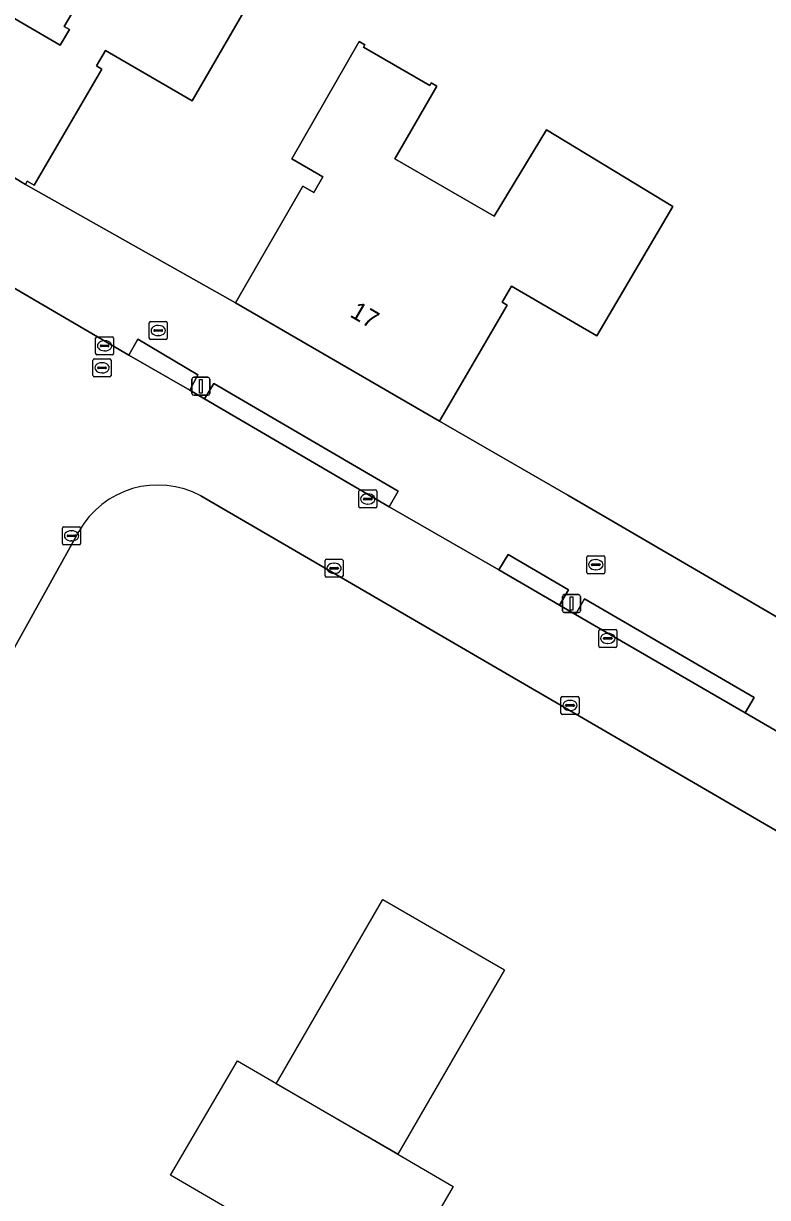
# Model space of a CAD drawing. Extents: x 156502 to 159075, y 384229 to 386100.
# Drawn here: x 157195.8 to 157237.2, y 385818.9 to 385884.2 of the extents above; entities that cross this region are included whole.
import ezdxf

# ---------------------------------------------------------------- set-up
doc = ezdxf.new("R2010")
doc.units = 0
for name, color, linetype in [('IMGEO_Brandkraan', 7, 'Continuous'), ('IMGEO_Erf', 7, 'Continuous'), ('IMGEO_Grasland_overig', 7, 'Continuous'), ('IMGEO_Groenvoorziening', 7, 'Continuous'), ('IMGEO_Haag', 7, 'Continuous'), ('IMGEO_Hek', 7, 'Continuous'), ('IMGEO_Kolk', 7, 'Continuous'), ('IMGEO_Lichtmast', 7, 'Continuous'), ('IMGEO_Pand', 7, 'Continuous'), ('IMGEO_Pand_nummerreeks', 7, 'Continuous'), ('IMGEO_Pand_vergunning_verleend', 7, 'Continuous'), ('IMGEO_Rijbaan_lokaal_open', 7, 'Continuous'), ('IMGEO_Rioolput', 7, 'Continuous'), ('IMGEO_Voetpad_open', 7, 'Continuous')]:
    doc.layers.add(name, color=color, linetype=linetype)

msp = doc.modelspace()

# ---------------------------------------------------------------- linework, layer by layer
at = {"layer": 'IMGEO_Brandkraan'}
for p, q in [((157227.135, 385853.685), (157227.135, 385854.537)), ((157227.21, 385854.611), (157228.062, 385854.611)), ((157227.623, 385854.391), (157227.648, 385854.391)), ((157228.136, 385854.537), (157228.136, 385853.685)), ((157227.394, 385854.105), (157227.394, 385854.117)), ((157227.832, 385854.068), (157227.434, 385854.068)), ((157227.437, 385854.154), (157227.835, 385854.154)), ((157227.646, 385853.831), (157227.621, 385853.831)), ((157227.878, 385854.117), (157227.878, 385854.105)), ((157228.062, 385853.611), (157227.21, 385853.611))]:
    msp.add_line(p, q, dxfattribs=at)
for points in [[(157227.135, 385853.685), (157227.135, 385854.537)], [(157227.21, 385854.611), (157228.062, 385854.611)], [(157228.136, 385854.537), (157228.136, 385853.685)], [(157228.062, 385853.611), (157227.21, 385853.611)]]:
    msp.add_lwpolyline(points, dxfattribs=at)
for centre, radius, start, end in [((157227.212, 385854.535), 0.0765, 91.55205, 178.44795), ((157227.212, 385854.535), 0.0765, 91.55205, 178.44795), ((157228.06, 385854.535), 0.0765, 1.55205, 88.44795), ((157228.06, 385854.535), 0.0765, 1.55205, 88.44795), ((157227.212, 385853.687), 0.0765, 181.55205, 268.44795), ((157227.212, 385853.687), 0.0765, 181.55205, 268.44795), ((157227.434, 385854.114), 0.0403, 85.87752, 175.75265), ((157227.431, 385854.104), 0.0366, 178.93798, 274.71019), ((157227.835, 385854.111), 0.043, 264.86636, 352.45326), ((157227.839, 385854.116), 0.0386, 1.73085, 96.63898), ((157228.06, 385853.687), 0.0765, 271.55205, 358.44795), ((157228.06, 385853.687), 0.0765, 271.55205, 358.44795)]:
    msp.add_arc(centre, radius, start, end, dxfattribs=at)
for centre, major_axis, ratio, start_param, end_param in [((157227.622, 385854.111), (-0.387, 0.002), 0.722429, 4.712389, 7.853982), ((157227.647, 385854.111), (-0.39, 0.002), 0.717154, 1.570796, 4.712389)]:
    msp.add_ellipse(centre, major_axis=major_axis, ratio=ratio, start_param=start_param, end_param=end_param, dxfattribs=at)
at = {"layer": 'IMGEO_Erf'}
for points in [[(157188.853, 385888.249), (157197.887, 385882.973), (157198.399, 385883.845), (157198.106, 385884.017), (157202.417, 385891.356)], [(157209.465, 385887.215), (157205.225, 385879.893), (157200.407, 385882.684), (157199.904, 385881.82), (157200.198, 385881.649), (157196.439, 385875.192), (157196.06, 385875.413), (157195.952, 385875.233), (157207.627, 385868.664), (157211.365, 385875.15), (157211.978, 385874.797), (157212.478, 385875.666), (157210.745, 385876.665), (157214.5, 385883.18), (157214.812, 385883), (157214.732, 385882.862), (157218.418, 385880.738), (157218.498, 385880.877), (157218.81, 385880.697), (157216.482, 385876.657), (157221.993, 385873.482), (157224.899, 385878.267), (157231.916, 385874.005), (157227.702, 385866.82), (157222.95, 385869.578), (157222.433, 385868.694), (157222.709, 385868.533), (157218.954, 385862.085), (157226.078, 385857.975), (157255.558, 385840.78)]]:
    msp.add_lwpolyline(points, dxfattribs=at)
at = {"layer": 'IMGEO_Grasland_overig'}
for points in [[(157272.043, 385820.045), (157260.436, 385826.723), (157250.702, 385832.309), (157250.457, 385831.882), (157205.703, 385857.935)], [(157198.923, 385855.959), (157184.675, 385830.26)]]:
    msp.add_lwpolyline(points, dxfattribs=at)
msp.add_arc((157203.316, 385853.505), 5.032, 61.68589, 150.81115, dxfattribs=at)
at = {"layer": 'IMGEO_Groenvoorziening'}
for points in [[(157205.084, 385863.813), (157205.541, 385864.654), (157202.208, 385866.645), (157201.692, 385865.761)], [(157216.161, 385857.317), (157216.666, 385858.188), (157206.425, 385864.182), (157205.901, 385863.335)], [(157225.619, 385851.871), (157226.118, 385852.71), (157222.769, 385854.683), (157222.254, 385853.823)], [(157227.001, 385852.219), (157226.506, 385851.343), (157235.934, 385845.88), (157236.427, 385846.73)]]:
    msp.add_lwpolyline(points, close=True, dxfattribs=at)
at = {"layer": 'IMGEO_Haag'}
for points in [[(157205.084, 385863.813), (157205.541, 385864.654), (157202.208, 385866.645), (157201.692, 385865.761)], [(157216.161, 385857.317), (157216.666, 385858.188), (157206.425, 385864.182), (157205.901, 385863.335)], [(157225.619, 385851.871), (157226.118, 385852.71), (157222.769, 385854.683), (157222.254, 385853.823)], [(157227.001, 385852.219), (157226.506, 385851.343), (157235.934, 385845.88), (157236.427, 385846.73)]]:
    msp.add_lwpolyline(points, close=True, dxfattribs=at)
at = {"layer": 'IMGEO_Hek'}
for points in [[(157195.952, 385875.233), (157207.627, 385868.664)], [(157218.954, 385862.085), (157226.078, 385857.975)]]:
    msp.add_lwpolyline(points, dxfattribs=at)
at = {"layer": 'IMGEO_Kolk'}
for p, q in [((157199.93, 385866.773), (157200.782, 385866.773)), ((157199.855, 385865.847), (157199.855, 385866.699)), ((157200.114, 385866.267), (157200.114, 385866.279)), ((157200.552, 385866.23), (157200.154, 385866.23)), ((157200.157, 385866.316), (157200.555, 385866.316)), ((157200.343, 385866.553), (157200.368, 385866.553)), ((157200.598, 385866.279), (157200.598, 385866.267)), ((157200.856, 385866.699), (157200.856, 385865.847)), ((157200.782, 385865.773), (157199.93, 385865.773)), ((157200.366, 385865.993), (157200.341, 385865.993)), ((157214.543, 385858.262), (157215.395, 385858.262)), ((157214.468, 385857.336), (157214.468, 385858.188)), ((157214.727, 385857.756), (157214.727, 385857.768)), ((157215.165, 385857.719), (157214.767, 385857.719)), ((157214.77, 385857.805), (157215.168, 385857.805)), ((157214.956, 385858.042), (157214.981, 385858.042)), ((157215.211, 385857.768), (157215.211, 385857.756)), ((157215.469, 385858.188), (157215.469, 385857.336)), ((157215.395, 385857.262), (157214.543, 385857.262)), ((157214.979, 385857.482), (157214.954, 385857.482)), ((157198.018, 385855.288), (157198.018, 385856.14)), ((157198.093, 385856.214), (157198.945, 385856.214)), ((157198.277, 385855.708), (157198.277, 385855.72)), ((157198.715, 385855.671), (157198.317, 385855.671)), ((157198.32, 385855.757), (157198.718, 385855.757)), ((157198.506, 385855.994), (157198.531, 385855.994)), ((157198.761, 385855.72), (157198.761, 385855.708)), ((157199.019, 385856.14), (157199.019, 385855.288)), ((157198.945, 385855.214), (157198.093, 385855.214)), ((157198.529, 385855.434), (157198.504, 385855.434)), ((157212.596, 385853.485), (157212.596, 385854.337)), ((157212.671, 385854.411), (157213.523, 385854.411)), ((157213.597, 385854.337), (157213.597, 385853.485)), ((157212.855, 385853.905), (157212.855, 385853.917)), ((157213.293, 385853.868), (157212.895, 385853.868)), ((157212.898, 385853.954), (157213.296, 385853.954)), ((157213.084, 385854.191), (157213.109, 385854.191)), ((157213.339, 385853.917), (157213.339, 385853.905)), ((157213.523, 385853.411), (157212.671, 385853.411)), ((157213.107, 385853.631), (157213.082, 385853.631)), ((157227.802, 385849.59), (157227.802, 385850.442)), ((157227.877, 385850.516), (157228.729, 385850.516)), ((157228.803, 385850.442), (157228.803, 385849.59)), ((157228.061, 385850.01), (157228.061, 385850.022)), ((157228.499, 385849.973), (157228.101, 385849.973)), ((157228.104, 385850.059), (157228.502, 385850.059)), ((157228.29, 385850.296), (157228.315, 385850.296)), ((157228.545, 385850.022), (157228.545, 385850.01)), ((157228.729, 385849.516), (157227.877, 385849.516)), ((157228.313, 385849.736), (157228.288, 385849.736)), ((157225.702, 385845.866), (157225.702, 385846.718)), ((157225.777, 385846.792), (157226.629, 385846.792)), ((157226.19, 385846.572), (157226.215, 385846.572)), ((157226.703, 385846.718), (157226.703, 385845.866)), ((157225.961, 385846.286), (157225.961, 385846.298)), ((157226.399, 385846.249), (157226.001, 385846.249)), ((157226.004, 385846.335), (157226.402, 385846.335)), ((157226.213, 385846.012), (157226.188, 385846.012)), ((157226.445, 385846.298), (157226.445, 385846.286)), ((157226.629, 385845.792), (157225.777, 385845.792))]:
    msp.add_line(p, q, dxfattribs=at)
for points in [[(157199.93, 385866.773), (157200.782, 385866.773)], [(157199.855, 385865.847), (157199.855, 385866.699)], [(157200.856, 385866.699), (157200.856, 385865.847)], [(157200.782, 385865.773), (157199.93, 385865.773)], [(157214.543, 385858.262), (157215.395, 385858.262)], [(157214.468, 385857.336), (157214.468, 385858.188)], [(157215.469, 385858.188), (157215.469, 385857.336)], [(157215.395, 385857.262), (157214.543, 385857.262)], [(157198.018, 385855.288), (157198.018, 385856.14)], [(157198.093, 385856.214), (157198.945, 385856.214)], [(157199.019, 385856.14), (157199.019, 385855.288)], [(157198.945, 385855.214), (157198.093, 385855.214)], [(157212.596, 385853.485), (157212.596, 385854.337)], [(157212.671, 385854.411), (157213.523, 385854.411)], [(157213.597, 385854.337), (157213.597, 385853.485)], [(157213.523, 385853.411), (157212.671, 385853.411)], [(157227.802, 385849.59), (157227.802, 385850.442)], [(157227.877, 385850.516), (157228.729, 385850.516)], [(157228.803, 385850.442), (157228.803, 385849.59)], [(157228.729, 385849.516), (157227.877, 385849.516)], [(157225.702, 385845.866), (157225.702, 385846.718)], [(157225.777, 385846.792), (157226.629, 385846.792)], [(157226.703, 385846.718), (157226.703, 385845.866)], [(157226.629, 385845.792), (157225.777, 385845.792)]]:
    msp.add_lwpolyline(points, dxfattribs=at)
for centre, radius, start, end in [((157199.932, 385866.697), 0.0765, 91.55205, 178.44795), ((157199.932, 385866.697), 0.0765, 91.55205, 178.44795), ((157200.78, 385866.697), 0.0765, 1.55205, 88.44795), ((157200.78, 385866.697), 0.0765, 1.55205, 88.44795), ((157200.154, 385866.276), 0.0403, 85.87752, 175.75265), ((157200.151, 385866.266), 0.0366, 178.93798, 274.71019), ((157200.555, 385866.273), 0.043, 264.86636, 352.45326), ((157200.559, 385866.278), 0.0386, 1.73085, 96.63898), ((157199.932, 385865.849), 0.0765, 181.55205, 268.44795), ((157199.932, 385865.849), 0.0765, 181.55205, 268.44795), ((157200.78, 385865.849), 0.0765, 271.55205, 358.44795), ((157200.78, 385865.849), 0.0765, 271.55205, 358.44795), ((157214.545, 385858.186), 0.0765, 91.55205, 178.44795), ((157214.545, 385858.186), 0.0765, 91.55205, 178.44795), ((157215.393, 385858.186), 0.0765, 1.55205, 88.44795), ((157215.393, 385858.186), 0.0765, 1.55205, 88.44795), ((157214.767, 385857.765), 0.0403, 85.87752, 175.75265), ((157214.764, 385857.755), 0.0366, 178.93798, 274.71019), ((157215.168, 385857.762), 0.043, 264.86636, 352.45326), ((157215.172, 385857.767), 0.0386, 1.73085, 96.63898), ((157214.545, 385857.338), 0.0765, 181.55205, 268.44795), ((157214.545, 385857.338), 0.0765, 181.55205, 268.44795), ((157215.393, 385857.338), 0.0765, 271.55205, 358.44795), ((157215.393, 385857.338), 0.0765, 271.55205, 358.44795), ((157198.095, 385856.138), 0.0765, 91.55205, 178.44795), ((157198.095, 385856.138), 0.0765, 91.55205, 178.44795), ((157198.317, 385855.717), 0.0403, 85.87752, 175.75265), ((157198.314, 385855.707), 0.0366, 178.93798, 274.71019), ((157198.718, 385855.714), 0.043, 264.86636, 352.45326), ((157198.722, 385855.719), 0.0386, 1.73085, 96.63898), ((157198.943, 385856.138), 0.0765, 1.55205, 88.44795), ((157198.943, 385856.138), 0.0765, 1.55205, 88.44795), ((157198.095, 385855.29), 0.0765, 181.55205, 268.44795), ((157198.095, 385855.29), 0.0765, 181.55205, 268.44795), ((157198.943, 385855.29), 0.0765, 271.55205, 358.44795), ((157198.943, 385855.29), 0.0765, 271.55205, 358.44795), ((157212.673, 385854.335), 0.0765, 91.55205, 178.44795), ((157212.673, 385854.335), 0.0765, 91.55205, 178.44795), ((157213.521, 385854.335), 0.0765, 1.55205, 88.44795), ((157213.521, 385854.335), 0.0765, 1.55205, 88.44795), ((157212.895, 385853.914), 0.0403, 85.87752, 175.75265), ((157212.892, 385853.904), 0.0366, 178.93798, 274.71019), ((157213.296, 385853.911), 0.043, 264.86636, 352.45326), ((157213.3, 385853.916), 0.0386, 1.73085, 96.63898), ((157212.673, 385853.487), 0.0765, 181.55205, 268.44795), ((157212.673, 385853.487), 0.0765, 181.55205, 268.44795), ((157213.521, 385853.487), 0.0765, 271.55205, 358.44795), ((157213.521, 385853.487), 0.0765, 271.55205, 358.44795), ((157227.879, 385850.44), 0.0765, 91.55205, 178.44795), ((157227.879, 385850.44), 0.0765, 91.55205, 178.44795), ((157228.727, 385850.44), 0.0765, 1.55205, 88.44795), ((157228.727, 385850.44), 0.0765, 1.55205, 88.44795), ((157228.101, 385850.019), 0.0403, 85.87752, 175.75265), ((157228.098, 385850.009), 0.0366, 178.93798, 274.71019), ((157228.502, 385850.016), 0.043, 264.86636, 352.45326), ((157228.506, 385850.021), 0.0386, 1.73085, 96.63898), ((157227.879, 385849.592), 0.0765, 181.55205, 268.44795), ((157227.879, 385849.592), 0.0765, 181.55205, 268.44795), ((157228.727, 385849.592), 0.0765, 271.55205, 358.44795), ((157228.727, 385849.592), 0.0765, 271.55205, 358.44795), ((157225.779, 385846.716), 0.0765, 91.55205, 178.44795), ((157225.779, 385846.716), 0.0765, 91.55205, 178.44795), ((157226.627, 385846.716), 0.0765, 1.55205, 88.44795), ((157226.627, 385846.716), 0.0765, 1.55205, 88.44795), ((157225.779, 385845.868), 0.0765, 181.55205, 268.44795), ((157225.779, 385845.868), 0.0765, 181.55205, 268.44795), ((157226.001, 385846.295), 0.0403, 85.87752, 175.75265), ((157225.998, 385846.285), 0.0366, 178.93798, 274.71019), ((157226.402, 385846.292), 0.043, 264.86636, 352.45326), ((157226.406, 385846.297), 0.0386, 1.73085, 96.63898), ((157226.627, 385845.868), 0.0765, 271.55205, 358.44795), ((157226.627, 385845.868), 0.0765, 271.55205, 358.44795)]:
    msp.add_arc(centre, radius, start, end, dxfattribs=at)
for centre, major_axis, ratio, start_param, end_param in [((157200.342, 385866.273), (-0.387, 0.002), 0.722429, 4.712389, 7.853982), ((157200.367, 385866.273), (-0.39, 0.002), 0.717154, 1.570796, 4.712389), ((157214.955, 385857.762), (-0.387, 0.002), 0.722429, 4.712389, 7.853982), ((157214.98, 385857.762), (-0.39, 0.002), 0.717154, 1.570796, 4.712389), ((157198.505, 385855.714), (-0.387, 0.002), 0.722429, 4.712389, 7.853982), ((157198.53, 385855.714), (-0.39, 0.002), 0.717154, 1.570796, 4.712389), ((157213.083, 385853.911), (-0.387, 0.002), 0.722429, 4.712389, 7.853982), ((157213.108, 385853.911), (-0.39, 0.002), 0.717154, 1.570796, 4.712389), ((157228.289, 385850.016), (-0.387, 0.002), 0.722429, 4.712389, 7.853982), ((157228.314, 385850.016), (-0.39, 0.002), 0.717154, 1.570796, 4.712389), ((157226.189, 385846.292), (-0.387, 0.002), 0.722429, 4.712389, 7.853982), ((157226.214, 385846.292), (-0.39, 0.002), 0.717154, 1.570796, 4.712389)]:
    msp.add_ellipse(centre, major_axis=major_axis, ratio=ratio, start_param=start_param, end_param=end_param, dxfattribs=at)
at = {"layer": 'IMGEO_Lichtmast'}
for p, q in [((157205.203, 385863.623), (157205.203, 385864.423)), ((157205.203, 385864.423), (157205.203, 385863.623)), ((157205.303, 385864.523), (157206.093, 385864.523)), ((157206.093, 385864.523), (157205.303, 385864.523)), ((157206.193, 385864.423), (157206.193, 385863.623)), ((157206.193, 385863.623), (157206.193, 385864.423)), ((157206.093, 385863.523), (157205.303, 385863.523)), ((157205.303, 385863.523), (157206.093, 385863.523)), ((157225.888, 385852.452), (157226.678, 385852.452)), ((157226.678, 385852.452), (157225.888, 385852.452)), ((157225.788, 385851.552), (157225.788, 385852.352)), ((157225.788, 385852.352), (157225.788, 385851.552)), ((157226.778, 385852.352), (157226.778, 385851.552)), ((157226.778, 385851.552), (157226.778, 385852.352)), ((157226.678, 385851.452), (157225.888, 385851.452)), ((157225.888, 385851.452), (157226.678, 385851.452))]:
    msp.add_line(p, q, dxfattribs=at)
for points in [[(157205.623, 385864.398), (157205.773, 385864.398), (157205.773, 385863.648), (157205.623, 385863.648), (157205.623, 385864.398)], [(157226.208, 385852.327), (157226.358, 385852.327), (157226.358, 385851.577), (157226.208, 385851.577), (157226.208, 385852.327)]]:
    msp.add_lwpolyline(points, dxfattribs=at)
for centre, start, end in [((157205.303, 385864.423), 90, 180), ((157205.303, 385864.423), 90, 180), ((157206.093, 385864.423), 0, 90), ((157206.093, 385864.423), 360, 90), ((157205.303, 385863.623), 180, 270), ((157205.303, 385863.623), 180, 270), ((157206.093, 385863.623), 270, 0), ((157206.093, 385863.623), 270, 0), ((157225.888, 385852.352), 90, 180), ((157225.888, 385852.352), 90, 180), ((157226.678, 385852.352), 0, 90), ((157226.678, 385852.352), 360, 90), ((157225.888, 385851.552), 180, 270), ((157225.888, 385851.552), 180, 270), ((157226.678, 385851.552), 270, 0), ((157226.678, 385851.552), 270, 0)]:
    msp.add_arc(centre, 0.1, start, end, dxfattribs=at)
at = {"layer": 'IMGEO_Pand'}
for points in [[(157195.952, 385875.233), (157196.06, 385875.413), (157196.439, 385875.192), (157200.198, 385881.649), (157199.904, 385881.82), (157200.407, 385882.684), (157205.225, 385879.893), (157209.465, 385887.215), (157202.417, 385891.356), (157198.106, 385884.017), (157198.399, 385883.845), (157197.887, 385882.973), (157188.853, 385888.249), (157185.093, 385881.809)], [(157231.916, 385874.005), (157224.899, 385878.267), (157221.993, 385873.482), (157216.482, 385876.657), (157218.81, 385880.697), (157218.498, 385880.877), (157218.418, 385880.738), (157214.732, 385882.862), (157214.812, 385883), (157214.5, 385883.18), (157210.745, 385876.665), (157212.478, 385875.666), (157211.978, 385874.797), (157211.365, 385875.15), (157207.627, 385868.664), (157218.954, 385862.085), (157222.709, 385868.533), (157222.433, 385868.694), (157222.95, 385869.578), (157227.702, 385866.82)]]:
    msp.add_lwpolyline(points, close=True, dxfattribs=at)
at = {"layer": 'IMGEO_Pand_vergunning_verleend'}
for points in [[(157209.879, 385825.265), (157215.806, 385835.51), (157222.569, 385831.597), (157216.642, 385821.353)], [(157204.018, 385820.184), (157207.727, 385826.548), (157209.872, 385825.298), (157216.642, 385821.353), (157219.712, 385819.564), (157216.003, 385813.2)]]:
    msp.add_lwpolyline(points, close=True, dxfattribs=at)
at = {"layer": 'IMGEO_Rijbaan_lokaal_open'}
for points in [[(157205.703, 385857.935), (157250.457, 385831.882), (157250.702, 385832.309), (157252.582, 385835.588), (157249.263, 385837.527), (157249.511, 385837.937), (157247.026, 385839.395), (157246.178, 385839.897), (157241.947, 385842.373), (157235.934, 385845.88), (157226.506, 385851.343), (157225.619, 385851.871), (157222.254, 385853.823), (157216.161, 385857.317), (157205.901, 385863.335), (157205.084, 385863.813), (157201.692, 385865.761), (157193.644, 385870.453), (157185.088, 385875.436), (157184.271, 385875.92), (157179.189, 385878.901), (157172.275, 385882.9)], [(157184.675, 385830.26), (157198.923, 385855.959)]]:
    msp.add_lwpolyline(points, dxfattribs=at)
msp.add_arc((157203.316, 385853.505), 5.032, 61.68589, 150.81115, dxfattribs=at)
at = {"layer": 'IMGEO_Rioolput'}
for p, q in [((157202.834, 385866.696), (157202.834, 385867.548)), ((157202.909, 385867.622), (157203.761, 385867.622)), ((157203.322, 385867.402), (157203.347, 385867.402)), ((157203.835, 385867.548), (157203.835, 385866.696)), ((157203.093, 385867.116), (157203.093, 385867.128)), ((157203.531, 385867.079), (157203.133, 385867.079)), ((157203.136, 385867.165), (157203.534, 385867.165)), ((157203.345, 385866.842), (157203.32, 385866.842)), ((157203.577, 385867.128), (157203.577, 385867.116)), ((157203.761, 385866.622), (157202.909, 385866.622)), ((157199.709, 385864.624), (157199.709, 385865.476)), ((157199.784, 385865.55), (157200.636, 385865.55)), ((157200.71, 385865.476), (157200.71, 385864.624)), ((157199.968, 385865.044), (157199.968, 385865.056)), ((157200.406, 385865.007), (157200.008, 385865.007)), ((157200.011, 385865.093), (157200.409, 385865.093)), ((157200.197, 385865.33), (157200.222, 385865.33)), ((157200.452, 385865.056), (157200.452, 385865.044)), ((157200.636, 385864.55), (157199.784, 385864.55)), ((157200.22, 385864.77), (157200.195, 385864.77))]:
    msp.add_line(p, q, dxfattribs=at)
for points in [[(157202.834, 385866.696), (157202.834, 385867.548)], [(157202.909, 385867.622), (157203.761, 385867.622)], [(157203.835, 385867.548), (157203.835, 385866.696)], [(157203.761, 385866.622), (157202.909, 385866.622)], [(157199.709, 385864.624), (157199.709, 385865.476)], [(157199.784, 385865.55), (157200.636, 385865.55)], [(157200.71, 385865.476), (157200.71, 385864.624)], [(157200.636, 385864.55), (157199.784, 385864.55)]]:
    msp.add_lwpolyline(points, dxfattribs=at)
for centre, radius, start, end in [((157202.911, 385867.546), 0.0765, 91.55205, 178.44795), ((157202.911, 385867.546), 0.0765, 91.55205, 178.44795), ((157203.759, 385867.546), 0.0765, 1.55205, 88.44795), ((157203.759, 385867.546), 0.0765, 1.55205, 88.44795), ((157203.133, 385867.125), 0.0403, 85.87752, 175.75265), ((157203.13, 385867.115), 0.0366, 178.93798, 274.71019), ((157203.534, 385867.122), 0.043, 264.86636, 352.45326), ((157203.538, 385867.127), 0.0386, 1.73085, 96.63898), ((157202.911, 385866.698), 0.0765, 181.55205, 268.44795), ((157202.911, 385866.698), 0.0765, 181.55205, 268.44795), ((157203.759, 385866.698), 0.0765, 271.55205, 358.44795), ((157203.759, 385866.698), 0.0765, 271.55205, 358.44795), ((157199.786, 385865.474), 0.0765, 91.55205, 178.44795), ((157199.786, 385865.474), 0.0765, 91.55205, 178.44795), ((157200.634, 385865.474), 0.0765, 1.55205, 88.44795), ((157200.634, 385865.474), 0.0765, 1.55205, 88.44795), ((157200.008, 385865.053), 0.0403, 85.87752, 175.75265), ((157200.005, 385865.043), 0.0366, 178.93798, 274.71019), ((157200.409, 385865.05), 0.043, 264.86636, 352.45326), ((157200.413, 385865.055), 0.0386, 1.73085, 96.63898), ((157199.786, 385864.626), 0.0765, 181.55205, 268.44795), ((157199.786, 385864.626), 0.0765, 181.55205, 268.44795), ((157200.634, 385864.626), 0.0765, 271.55205, 358.44795), ((157200.634, 385864.626), 0.0765, 271.55205, 358.44795)]:
    msp.add_arc(centre, radius, start, end, dxfattribs=at)
for centre, major_axis, ratio, start_param, end_param in [((157203.321, 385867.122), (-0.387, 0.002), 0.722429, 4.712389, 7.853982), ((157203.346, 385867.122), (-0.39, 0.002), 0.717154, 1.570796, 4.712389), ((157200.196, 385865.05), (-0.387, 0.002), 0.722429, 4.712389, 7.853982), ((157200.221, 385865.05), (-0.39, 0.002), 0.717154, 1.570796, 4.712389)]:
    msp.add_ellipse(centre, major_axis=major_axis, ratio=ratio, start_param=start_param, end_param=end_param, dxfattribs=at)
at = {"layer": 'IMGEO_Voetpad_open'}
for points in [[(157226.078, 385857.975), (157218.954, 385862.085), (157207.627, 385868.664), (157195.952, 385875.233), (157185.093, 385881.809), (157167.911, 385891.794), (157163.686, 385894.272), (157153.769, 385900.007), (157142.433, 385906.61), (157136.759, 385909.918), (157130.978, 385913.286), (157125.953, 385904.606), (157125.678, 385904.13), (157120.993, 385896.017), (157120.156, 385894.568), (157117.68, 385890.28), (157119.669, 385889.108)], [(157193.644, 385870.453), (157201.692, 385865.761), (157202.208, 385866.645), (157205.541, 385864.654), (157205.084, 385863.813), (157205.901, 385863.335), (157206.425, 385864.182), (157216.666, 385858.188), (157216.161, 385857.317), (157222.254, 385853.823), (157222.769, 385854.683), (157226.118, 385852.71), (157225.619, 385851.871), (157226.506, 385851.343), (157227.001, 385852.219), (157236.427, 385846.73), (157235.934, 385845.88), (157241.947, 385842.373)], [(157255.558, 385840.78), (157226.078, 385857.975)]]:
    msp.add_lwpolyline(points, dxfattribs=at)

# ---------------------------------------------------------------- texts
at = {"layer": 'IMGEO_Pand_nummerreeks'}
msp.add_text('17', height=1, rotation=329.85096, dxfattribs=at).set_placement((157213.923, 385867.921))

doc.saveas('drawing.dxf')
